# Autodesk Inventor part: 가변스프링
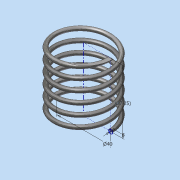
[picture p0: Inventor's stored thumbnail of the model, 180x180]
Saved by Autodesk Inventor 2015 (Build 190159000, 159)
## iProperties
Created: 2018-02
Part Number: 가변스프링
Material: 스테인레스 스틸
Document SubType Name: Modeling
Designer: SCD-A03
Mass: 42.1841 g
Surface Area: 70.9989 cm^2
Volume: 5.27301 cm^3
Density: 8 g/cm^3
Appearance: 반연마
Author: SCD-A03
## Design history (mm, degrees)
sketch "스케치1"
  geometry: L1 (0, 0)-(20, 0); L2 (20, 0)-(20, 47.25); L3 (20, 47.25)-(0, 47.25); L4 (0, 47.25)-(0, 0); C1 r 1.5 at (20, 0)
  constraints: 8 end point, 2 parallel, 1 centre point, 1 coincident, 1 horizontal, 1 perpendicular
  dimensions: "d0" = 40 diameter of L2 L4; "d1" = 47.25 distance of L1.end L2.end (derived); "d2" = 3 diameter of C1
feature "코일1" pitch "d3" = 10; turns "d5" = 6; dims "d4" = 47.25 (= d1), "d6" = 0, angle "d7" = 90 deg, angle "d8" = 90 deg, "d9" = 0, "d10" = 0
node "작업 평면1"
node "작업 평면2"
sketch "스케치2"
  geometry: L1 (18.5, 0)-(21.5, 0) reference; 1 further point
  constraints: 1 horizontal alignment
extrude "돌출1" cut sketch "스케치2" stored distance "d13" = 10; taper "d14" = 0 deg
sketch "스케치3"
  geometry: L1 (1.5, 0)-(-1.5, 0) reference; 1 further point
  constraints: 1 horizontal alignment
extrude "돌출2" cut sketch "스케치3" stored distance "d15" = 10; taper "d16" = 0 deg
node "솔리드1"
node "절단 모서리 투영1"
node "절단 모서리 투영2"
other parameters: "d11" = 90 deg, "d12" = 90 deg
